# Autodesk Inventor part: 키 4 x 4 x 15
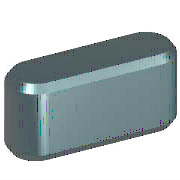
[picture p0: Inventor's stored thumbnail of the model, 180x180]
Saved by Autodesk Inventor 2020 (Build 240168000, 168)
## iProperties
Created: 2012-02
Part Number: 키 4 x 4 x 15
Material: 강철, 연강
Description: 키 및 해당 키홈
Document SubType Name: Modeling
Standard: KS B 1311
Designer: test
Standards Organization: KS
Language: ko-KR
Size Designation: 4 x 4 x 10
Categories: <MemberInstance><Categories><Category DisplayName="샤프트 부품" InternalName="7f7aeb1f-a693-4053-b835-cee3144e0d98" Mnemonic="SHFT"><Category DisplayName="키" Interna
Density: 1 g/cm^3
Appearance: 노란색
IsCustomPart: 1
Author: test
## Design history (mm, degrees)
workplane "Work Plane1"
workplane "Work Plane2"
sketch "스케치1"
  geometry: L1 (2, 2)-(13, 2); L2 (13, -2)-(2, -2); L3 (0, 8.8)-(0, -3.8) reference; L4 (-2, 0)-(12, 0) reference; L5 (15, 0)-(15, 7); A1 r 2 centre (2, 0) between (2, 2) and (2, -2); A2 r 2 centre (13, 0) between (13, -2) and (13, 2)
  constraints: 6 end point, 5 point on circle, 4 tangent, 3 point on line, 2 centre point, 1 horizontal, 1 parallel, 1 perpendicular
  dimensions: "d0" = 2 radius of A1 (= 0.5 x PB); "d13" = 2 radius of A2 (= 0.5 x PB); "d14" = 15 distance between parallel lines of L5 L3 (= NLG)
extrude "본체1" new body sketch "스케치1" taper "d3" = 0 deg; stored distance "d4" = 10
workplane "Work Plane3"
body "Solid1"
chamfer "모따기1" distance "d8" = 0.25 (= PHH); stored, may be unused: second distance "d9" = 0.25 (= PHH), angle "d15" = 45 deg
other parameters: "d1" = -2.5 (= -PNT), "d2" = 1.5 (= PH - PNT), "NLG" = 15 [user parameter; used in 3 equation terms], "PB" = 4 [user parameter; used in 2 equation terms], "PNT" = 2.5 [user parameter; used in 2 equation terms], "PH" = 4 [user parameter; used in 1 equation term], "PHH" = 0.25 [user parameter; used in 2 equation terms], "d10" = 0, "d16" = 0, "d17" = 0, "d18" = 0, "PLB2" = 15 (= NLG) [user parameter], "WDMAX" = 12 [user parameter], "PLB1" = 15 (= NLG) [user parameter], "RR" = 0.08 [user parameter], "PUEB" = 1.8 [user parameter]
